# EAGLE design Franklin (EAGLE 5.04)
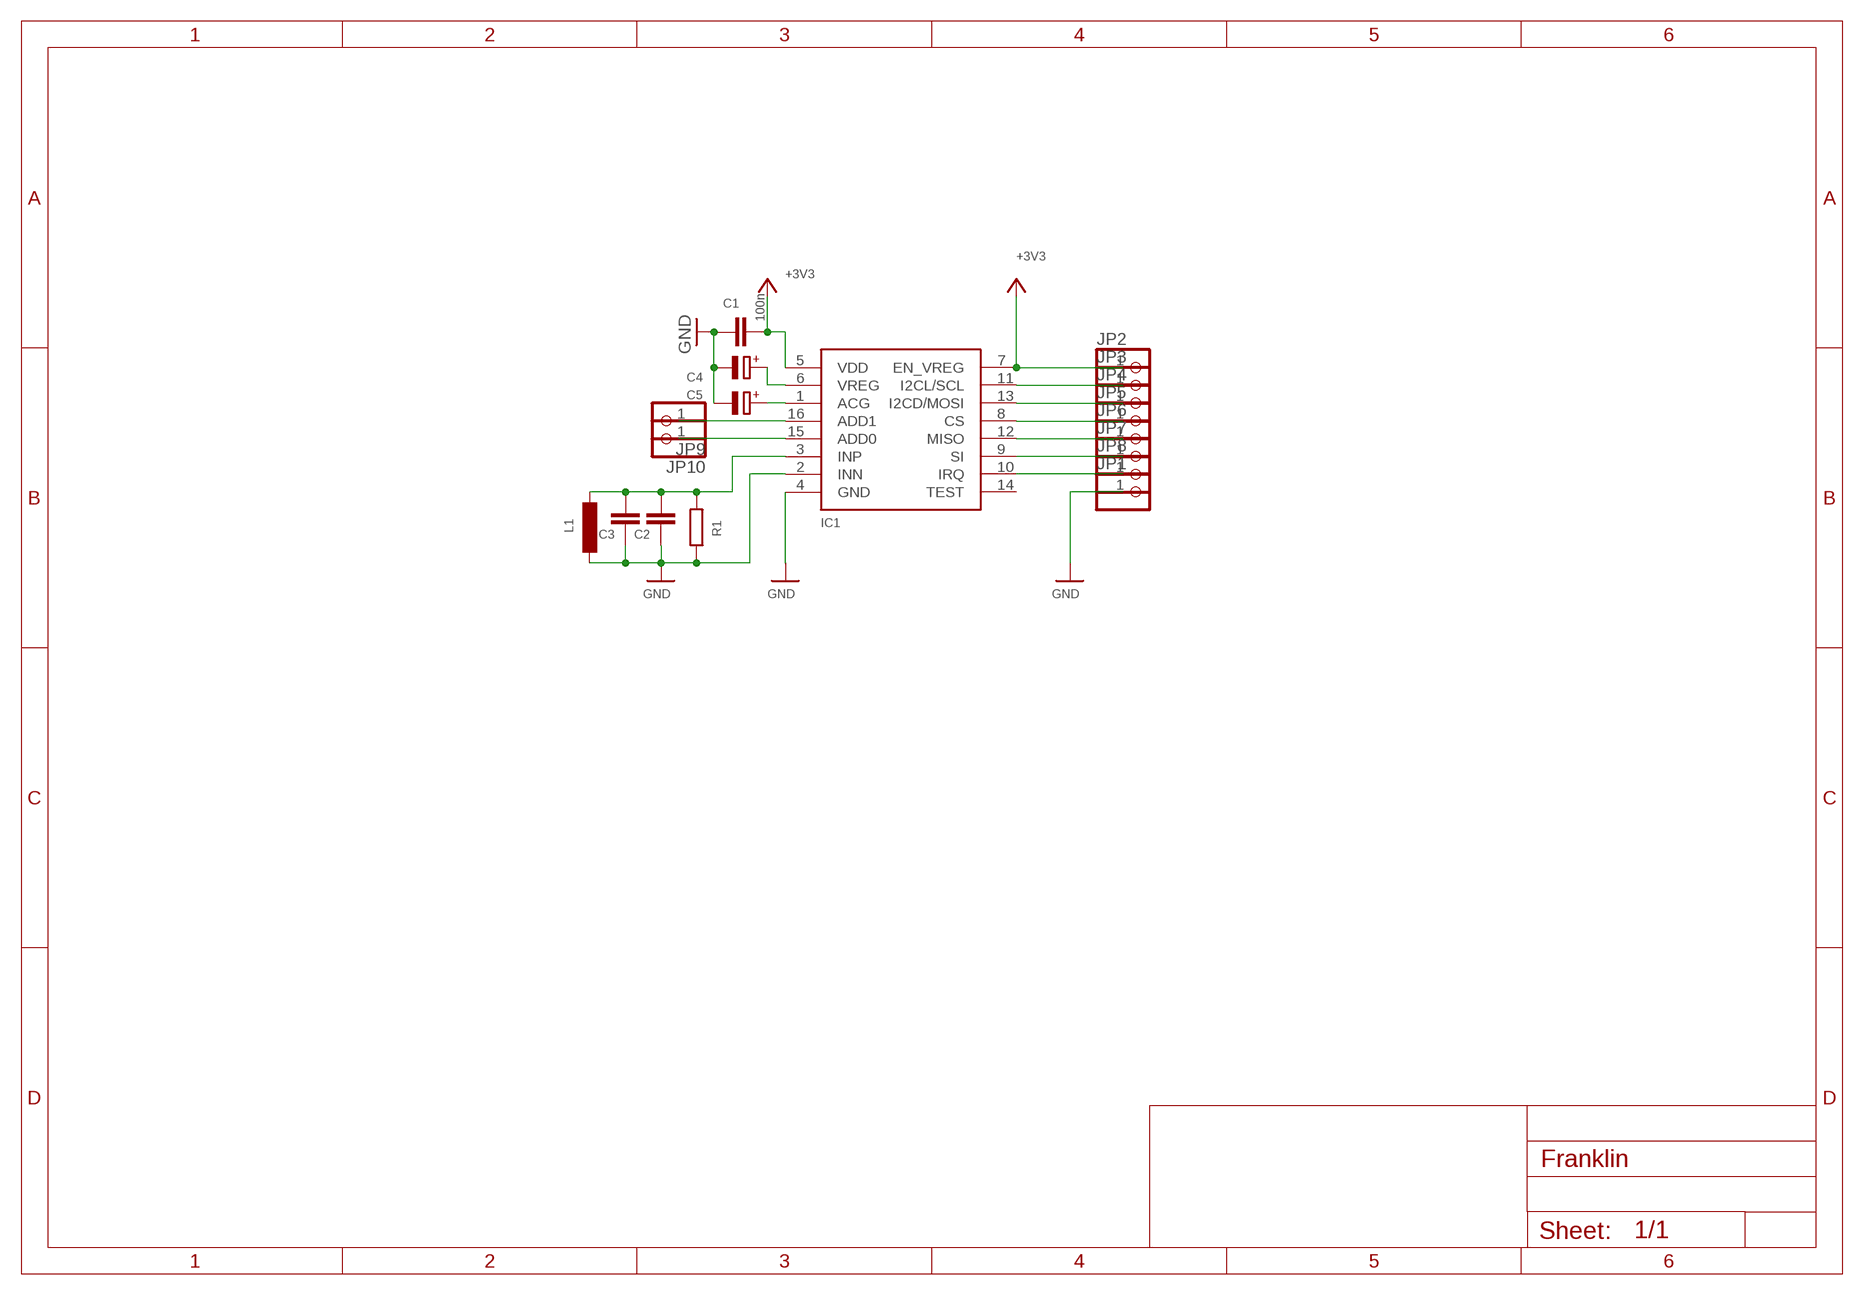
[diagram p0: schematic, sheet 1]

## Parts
C1  100n  C-EUC0805  [C0805]
C2  C-EUC0805  [C0805]
C3  C-EUC0805  [C0805]
C4  CPOL-EUA/3216-18R  [A/3216-18R]
C5  CPOL-EUA/3216-18R  [A/3216-18R]
IC1  AS3935  [QFN-16_4X4]
JP1  PINHD-1X1  [1X01]
JP2  PINHD-1X1  [1X01]
JP3  PINHD-1X1  [1X01]
JP4  PINHD-1X1  [1X01]
JP5  PINHD-1X1  [1X01]
JP6  PINHD-1X1  [1X01]
JP7  PINHD-1X1  [1X01]
JP8  PINHD-1X1  [1X01]
JP9  PINHD-1X1  [1X01]
JP10  PINHD-1X1  [1X01]
L1  L-EU0207/10  [0207/10]
R1  R-EU_R0805  [R0805]

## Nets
+3V3: C1.2 IC1.5(VDD) IC1.7(EN_VREG) JP2.1
GND: C1.1 C2.1 C3.1 C4.- C5.- IC1.2(INN) IC1.4(GND) JP1.1 L1.2 R1.1
N$1: IC1.10(IRQ) JP8.1
N$3: C2.2 C3.2 IC1.3(INP) L1.1 R1.2
N$4: IC1.12(MISO) JP6.1
N$5: IC1.8(CS) JP5.1
N$6: IC1.13(I2CD/MOSI) JP4.1
N$7: IC1.11(I2CL/SCL) JP3.1
N$8: IC1.15(ADD0) JP10.1
N$9: IC1.16(ADD1) JP9.1
N$10: C5.+ IC1.1(ACG)
N$11: C4.+ IC1.6(VREG)
N$12: IC1.9(SI) JP7.1
Unconnected: IC1.14(TEST)

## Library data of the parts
C1-C3 = rcl:C-EU: CAPACITOR, European symbol
C4 C5 = rcl:CPOL-EU: POLARIZED CAPACITOR, European symbol
IC1 = AMESYS:AS3935
JP1-JP10 = pinhead:PINHD-1X1: PIN HEADER
L1 = rcl:L-EU: INDUCTOR, European symbol
R1 = rcl:R-EU_: RESISTOR, European symbol

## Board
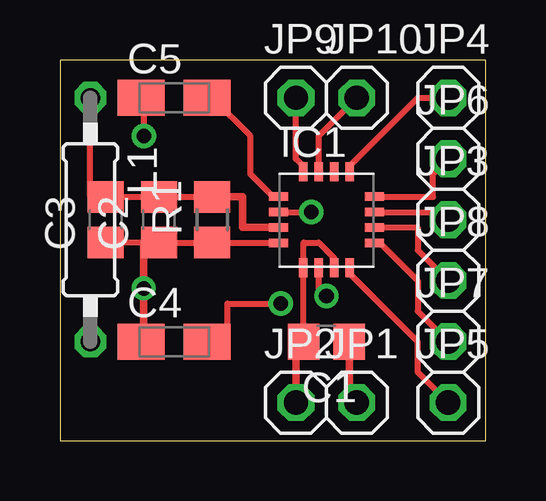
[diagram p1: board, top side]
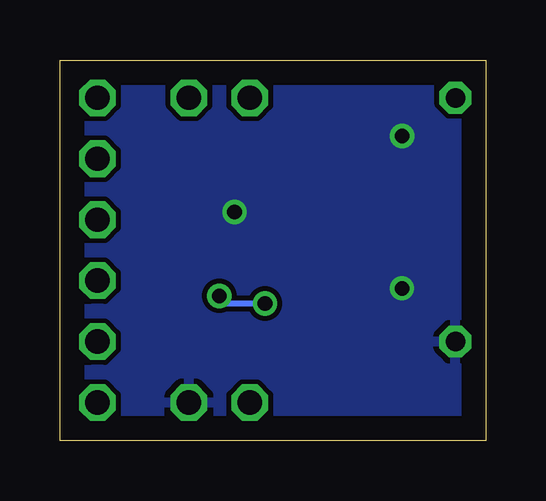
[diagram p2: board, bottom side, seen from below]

Size 17.76 x 15.86 mm. Coordinates in mm from the lower left corner, seen from the top.
Outline: 0,0 17.76,0 17.76,15.86 0,15.86 0,0
Copper layers (1*16): Top 0.035mm / dielectric 1.5mm / Bottom 0.035mm
Design rules "default": minimum track width 10mil, minimum drill 24mil, track to track 8mil, track to pad 8mil, pad to pad 8mil, via to via 8mil, smd to smd 8mil, copper to edge 40mil, drill to drill 8mil, minimum pad ring 10mil, minimum via ring 8mil, stop-mask expansion 4mil, vias tented up to drill 0mil, thermal gap 10mil

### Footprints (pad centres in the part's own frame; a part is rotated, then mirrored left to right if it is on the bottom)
C0805 = smd 1.3 x 1.5: 1 -0.95,0; 2 0.95,0
A/3216-18R = smd 1.95 x 1.5: + 1.375,0; - -1.375,0
QFN-16_4X4 = smd 0.8 x 0.35: 1 -2,0.975; 2 -2,0.325; 3 -2,-0.325; 4 -2,-0.975; 9 2,-0.975; 10 2,-0.325; 11 2,0.325; 12 2,0.975 | smd 0.35 x 0.8: 5 -0.975,-2; 6 -0.325,-2; 7 0.325,-2; 8 0.975,-2; 13 0.975,2; 14 0.325,2; 15 -0.325,2; 16 -0.975,2
1X01 = drill 1.016 octagon: 1 0,0
0207/10 = drill 0.813 octagon: 1 -5.08,0; 2 5.08,0
R0805 = smd 1.3 x 1.5: 1 -0.95,0; 2 0.95,0

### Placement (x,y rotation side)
C1  11.11,4.13 180 top
C2  4.13,9.21 90 top
C3  1.9,9.21 90 top
C4  4.76,4.13 0 top
C5  4.76,14.29 0 top
IC1  11.11,9.21 0 top
JP1  12.38,1.59 0 top
JP2  9.84,1.59 0 top
JP3  16.19,9.21 0 top
JP4  16.19,14.29 0 top
JP5  16.19,1.59 0 top
JP6  16.19,11.75 0 top
JP7  16.19,4.13 0 top
JP8  16.19,6.67 0 top
JP9  9.84,14.29 0 top
JP10  12.38,14.29 0 top
L1  1.27,9.21 270 top
R1  6.35,9.21 90 top

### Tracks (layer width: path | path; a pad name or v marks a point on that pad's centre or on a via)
+3V3
  Top 0.254: 9.84,3.81 10.48,4.13 C1.2 10.16,6.99 IC1.5 10.16,7.3 10.16,8.25 10.79,8.25 11.43,7.62 11.43,7.3 IC1.7
  Top 0.305: JP2.1 9.84,3.81
GND  (via drill 0.6, 0.61)
  Top 0.254: 6.03,8.25 8.89,8.25 IC1.4 | 8.89,9.52 IC1.2 9.21,9.52 v10.48,9.52 | 3.49,8.25 2.22,8.25 C3.1 | C4.- 3.49,4.13 | 3.49,8.25 6.03,8.25 | 6.03,8.25 R1.1 | 3.49,8.25 C2.1 | v3.49,12.7 3.49,14.29 C5.-
  Top 0.305: 3.49,8.25 v3.49,6.35 3.49,4.23 C4.- | C1.1 12.06,1.91 JP1.1 | IC1.4 9.13,8.25
  pour Bottom: -0.32,15.88 18.41,15.88 18.41,-0.32 -0.32,-0.32
N$1
  Top 0.254: JP8.1 14.92,7.94 14.92,8.89 13.33,8.89 IC1.10
N$3
  Top 0.254: 1.27,10.16 3.49,10.16 | 3.49,10.16 6.03,10.16 | 3.49,10.16 C2.2 | 9.21,8.89 IC1.3 | 1.27,10.16 L1.1 | C3.2 1.27,10.16
  Top 0.305: 9.21,8.89 7.62,8.89 7.62,10.16 6.03,10.16 R1.2
N$4
  Top 0.254: JP6.1 15.56,11.11 15.56,10.16 13.33,10.16 IC1.12
N$5
  Top 0.254: JP5.1 14.92,2.86 14.92,4.13 12.06,6.99 IC1.8
N$6
  Top 0.254: JP4.1 14.92,14.29 12.06,11.43 IC1.13
N$7
  Top 0.254: JP3.1 16.19,9.52 13.33,9.52 IC1.11
N$8
  Top 0.254: JP10.1 10.79,12.7 10.79,11.43 IC1.15
N$9
  Top 0.254: JP9.1 9.84,11.75 10.16,11.43 IC1.16
N$10
  Top 0.254: IC1.1 8.89,10.16 7.94,11.11 7.94,12.7 6.35,14.29 C5.+
N$11  (via drill 0.61)
  Top 0.254: 10.79,7.3 IC1.6 10.79,6.99 10.79,6.35 v11.11,6.03 | v9.21,5.72 6.99,5.72 6.99,4.76 C4.+
  Top 0.305: IC1.6
  Bottom 0.254: v11.11,6.03 10.79,5.72 v9.21,5.72
N$12
  Top 0.254: JP7.1 14.92,5.4 14.92,6.67 13.33,8.25 IC1.9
